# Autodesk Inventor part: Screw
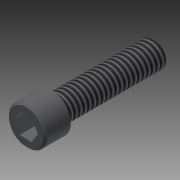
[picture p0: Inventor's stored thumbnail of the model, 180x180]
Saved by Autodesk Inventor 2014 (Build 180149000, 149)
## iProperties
Created: 2006-07
Part Number: Screw
Material: system_material_0
Description: SCREW, CAP, 1/4-20 X 3/8
Document SubType Name: Modeling
Designer: Z.MCGILL
Engineer: SAP
Manufacturer: Standard
Standards Organization: Custom
Mass: 26.2447 g
Surface Area: 18.9522 cm^2
Volume: 3.34682 cm^3
Density: 7.84168 g/cm^3
Appearance: system_RenderingStyle_0
NetWeight: 0.005
WeightUOM: KG
ModelCode: Comp
Author: Z.MCGILL
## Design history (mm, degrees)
node "SHCS"
body "Solid1"
tag "TaggingFeature2"
feature "DerivedBody::SHCS"
other parameters: "Thread_Length" = 31.75, "Head_Chamfer" = 0.635, "Thread_Chamfer" = 0.2286, "Thread_Diameter" = 7.9375, "Head_Diameter" = 11.90498, "Head_Length" = 7.9248, "Hex_Head_Width" = 6.35, "Hex_Head_Depth" = 6.35, "d23" = 0, "d24" = 0
